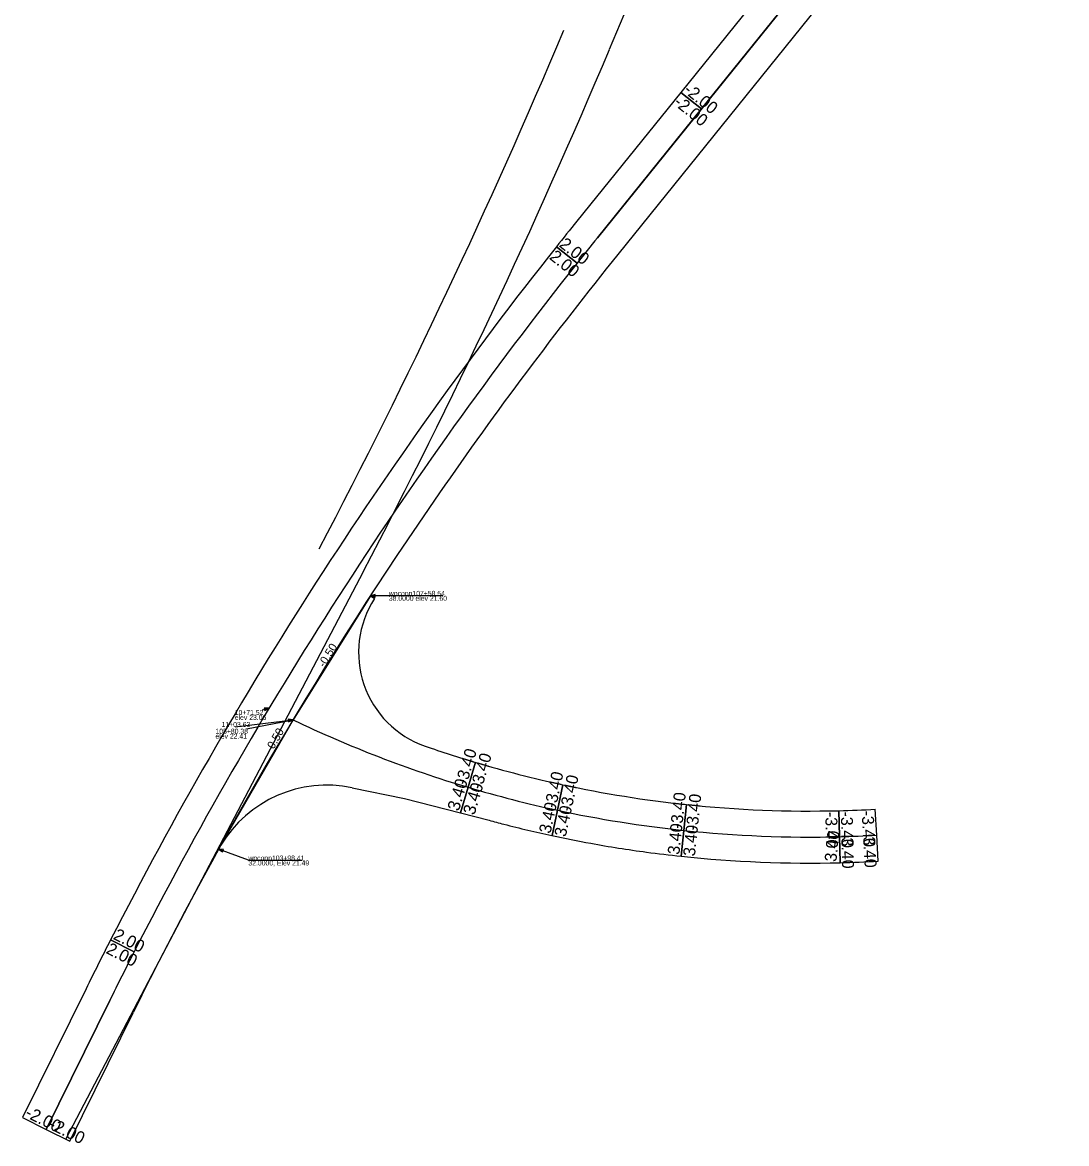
# Model space of a CAD drawing. Extents: x 2342222 to 2351711, y 366548 to 372860.
# Drawn here: x 2345362 to 2346628, y 366756 to 368114 of the extents above; entities that cross this region are included whole.
import ezdxf

# ---------------------------------------------------------------- set-up
doc = ezdxf.new("R2010")
doc.units = 0
for name, color, linetype in [('Default', 7, 'Continuous'), ('RD_HC_Cl', 7, 'Continuous'), ('RD_PD_RW_TX', 7, 'Continuous'), ('RD_PD_SuperShp_WP_CONN', 7, 'Continuous'), ('RD_Sketch4', 7, 'Continuous')]:
    doc.layers.add(name, color=color, linetype=linetype)

msp = doc.modelspace()

# ---------------------------------------------------------------- linework, layer by layer
at = {"layer": 'Default'}
for p, q in [((2345784.2, 367419.5), (2345789.2, 367416.2)), ((2346353.4, 367096.3), (2346351.8, 367159.3))]:
    msp.add_line(p, q, dxfattribs=at)
at = {"layer": 'RD_HC_Cl'}
for p, q in [((2346414.9, 368892.2), (2346073.6, 368081.3)), ((2346414.9, 368892.2), (2346073.6, 368081.3)), ((2345775.2, 367448.5), (2345415, 366761.9)), ((2345775.2, 367448.5), (2345415, 366761.9))]:
    msp.add_line(p, q, dxfattribs=at)
for radius in [8200, 8200, 8260, 8260]:
    msp.add_arc((2338460.5, 371285.5), radius, 332.32074, 337.175, dxfattribs=at)
at = {"layer": 'RD_PD_RW_TX'}
for p, q in [((2345872, 367419.5), (2345806.5, 367419.5)), ((2345701.2, 367098.9), (2345636.3, 367098.9))]:
    msp.add_line(p, q, dxfattribs=at)
for points in [[(2345790, 367421), (2345784.2, 367419.5), (2345790, 367417.9)], [(2345656.4, 367280.5), (2345661.6, 367283.5), (2345655.6, 367283.5)], [(2345685, 367266.7), (2345690.4, 367269.3), (2345684.4, 367269.8)], [(2345684.8, 367267.1), (2345690.4, 367269.3), (2345684.5, 367270.2)], [(2345606.2, 367112.1), (2345600.2, 367112.6), (2345605.1, 367109.2)]]:
    msp.add_lwpolyline(points, close=True, dxfattribs=at)
for points in [[(2345872, 367419.5), (2345784.2, 367419.5)], [(2345653, 367281.2), (2345661.6, 367283.5)], [(2345620.3, 367260.7), (2345690.4, 367269.3)], [(2345634, 367258.5), (2345690.4, 367269.3)], [(2345636.3, 367099.1), (2345600.2, 367112.6)]]:
    msp.add_lwpolyline(points, dxfattribs=at)
at = {"layer": 'RD_PD_SuperShp_WP_CONN'}
for p, q in [((2346602.8, 368577.6), (2346160.3, 368029.3)), ((2346185.2, 368009.2), (2346627.7, 368557.5)), ((2346532.1, 368439), (2346059.3, 367853.2)), ((2346084.2, 367833.1), (2346557, 368418.9)), ((2346160.3, 368029.3), (2346034.4, 367873.3)), ((2346185.2, 368009.2), (2346160.3, 368029.3)), ((2346160.3, 368029.3), (2346185.2, 368009.2)), ((2346059.3, 367853.2), (2346185.2, 368009.2)), ((2346034.6, 367822.4), (2346009.5, 367842.3)), ((2346009.5, 367842.3), (2346034.6, 367822.4)), ((2345497.9, 366988.2), (2345469.4, 367002.7)), ((2345469.4, 367002.7), (2345497.9, 366988.2)), ((2345439.6, 366943.5), (2345362.5, 366787.4)), ((2345391.2, 366773.2), (2345468.3, 366929.3)), ((2345468.3, 366929.3), (2345391.2, 366773.2)), ((2345419.9, 366759.1), (2345497, 366915.1)), ((2345419.9, 366759.1), (2345497, 366915.1)), ((2345362.5, 366787.4), (2345391.2, 366773.2)), ((2345391.2, 366773.2), (2345419.9, 366759.1))]:
    msp.add_line(p, q, dxfattribs=at)
for radius, start, end in [(5028, 141.0938, 141.5467), (4996, 141.0938, 141.5467), (4996, 141.0938, 141.5467), (5028, 141.5467, 152.9409), (4964, 141.0938, 145.2627), (4996, 141.5467, 152.9409), (4996, 141.5467, 152.9409), (4964, 145.2627, 153.6971), (5028, 152.9409, 153.6971), (4996, 152.9409, 153.6971), (4996, 152.9409, 153.6971)]:
    msp.add_arc((2349947, 364715.5), radius, start, end, dxfattribs=at)
at = {"layer": 'RD_Sketch4'}
for p, q in [((2345784.2, 367419.5), (2345690.4, 367269.3)), ((2345789.2, 367416.2), (2345784.2, 367419.5)), ((2345690.4, 367269.3), (2345602.9, 367117.4)), ((2345902.5, 367187.6), (2345911.5, 367217.8)), ((2345911.5, 367217.8), (2345902.5, 367187.6)), ((2345761.9, 367187.1), (2345825.4, 367174)), ((2345893.2, 367156.5), (2345902.5, 367187.6)), ((2345902.5, 367187.6), (2345893.2, 367156.5)), ((2346010.8, 367159.9), (2346017.5, 367190.7)), ((2346017.5, 367190.7), (2346010.8, 367159.9)), ((2345825.4, 367174), (2345893.2, 367156.5)), ((2346004.2, 367129.1), (2346010.8, 367159.9)), ((2346010.8, 367159.9), (2346004.2, 367129.1)), ((2346163.9, 367135.4), (2346167.2, 367166.7)), ((2346167.2, 367166.7), (2346163.9, 367135.4)), ((2346352.6, 367127.8), (2346351.8, 367159.3)), ((2346351.8, 367159.3), (2346352.6, 367127.8)), ((2346397.7, 367129.6), (2346395.9, 367161.1)), ((2345893.2, 367156.5), (2345928, 367147.6)), ((2346160.6, 367104), (2346163.9, 367135.4)), ((2346163.9, 367135.4), (2346160.6, 367104)), ((2346353.4, 367096.3), (2346352.6, 367127.8)), ((2346352.6, 367127.8), (2346353.4, 367096.3)), ((2346399.5, 367098.2), (2346397.7, 367129.6))]:
    msp.add_line(p, q, dxfattribs=at)
for centre, radius, start, end in [((2345889.8, 367350.8), 120, 146.9941, 250.83), ((2346316.3, 368577.7), 1450.4, 244.4328, 253.4199), ((2346316.3, 368577.7), 1450.4, 244.4328, 253.4199), ((2346316.3, 368577.7), 1418.9, 250.83, 253.4199), ((2346316.3, 368577.7), 1418.9, 253.4199, 257.8395), ((2345731.6, 367040.2), 150, 78.3222, 149.0373), ((2346316.3, 368577.7), 1450.4, 253.4199, 257.8395), ((2346316.3, 368577.7), 1450.4, 253.4199, 257.8395), ((2346316.3, 368577.7), 1418.9, 257.8395, 263.9661), ((2346316.3, 368577.7), 1450.4, 257.8395, 263.9661), ((2346316.3, 368577.7), 1450.4, 257.8395, 263.9661), ((2346316.3, 368577.7), 1418.9, 263.9661, 271.4328), ((2346316.3, 368577.7), 1418.9, 271.4328, 273.2156), ((2346316.3, 368577.7), 1481.9, 254.8096, 255.5213), ((2346316.3, 368577.7), 1481.9, 255.5213, 257.8395), ((2346316.3, 368577.7), 1450.4, 263.9661, 271.4328), ((2346316.3, 368577.7), 1450.4, 263.9661, 271.4328), ((2346316.3, 368577.7), 1481.9, 257.8395, 259.6918), ((2346316.3, 368577.7), 1481.9, 259.6918, 262.3405), ((2346316.3, 368577.7), 1450.4, 271.4328, 273.2156), ((2346316.3, 368577.7), 1450.4, 271.4328, 273.2156), ((2346316.3, 368577.7), 1481.9, 262.3405, 263.9661), ((2346316.3, 368577.7), 1481.9, 263.9661, 271.4328), ((2346316.3, 368577.7), 1481.9, 271.4328, 273.2156)]:
    msp.add_arc(centre, radius, start, end, dxfattribs=at)

# ---------------------------------------------------------------- texts
at = {"layer": 'Default'}
msp.add_text('105+80.38', height=0.00975, rotation=90, dxfattribs=at).set_placement((2345661.7, 367259.6))
msp.add_text('-.004', height=0.00975, dxfattribs=at).set_placement((2345654.6, 367222.7))
at = {"layer": 'RD_PD_RW_TX'}
for s, p in [('wpconn107+58.54', (2345806.5, 367419.5)), ('38.0000 elev 21.60', (2345806.5, 367413.5)), ('10+71.52', (2345619.8, 367275.2)), ('11+03.63', (2345603.8, 367260.7)), ('elev 23.06', (2345619.8, 367269.2)), ('elev 22.41', (2345596.4, 367246.5)), ('105+80.38', (2345596.4, 367252.5)), ('wpconn103+98.41', (2345636.3, 367098.9)), ('32.0000, Elev 21.49', (2345636.3, 367092.9))]:
    msp.add_text(s, height=6, dxfattribs=at).set_placement(p)
at = {"layer": 'RD_PD_SuperShp_WP_CONN'}
for s, rotation, p in [('-2.00', 321.0938, (2346162.7, 368030.2)), ('-2.00', 321.0938, (2346150.6, 368015.3)), ('2.00', 321.5467, (2346011.9, 367843.2)), ('2.00', 321.5467, (2346000, 367828.2)), ('2.00', 332.9409, (2345471.6, 367004.2)), ('2.00', 332.9409, (2345462.8, 366987.1)), ('-2.00', 333.6971, (2345364.6, 366788.9)), ('-2.00', 333.6971, (2345393.3, 366774.7))]:
    msp.add_text(s, height=14.72, rotation=rotation, dxfattribs=at).set_placement(p)
at = {"layer": 'RD_Sketch4'}
for s, height, rotation, p in [('-0.50', 10, 58.0157, (2345728.4, 367332)), ('-0.50', 10, 60.0807, (2345664.7, 367229.2)), ('-3.40', 14.49, 73.4199, (2345900.7, 367189.5)), ('-3.40', 14.49, 73.4199, (2345918.8, 367184.1)), ('-3.40', 14.49, 77.8395, (2346008.9, 367161.6)), ('-3.40', 14.49, 77.8395, (2346027.4, 367157.6)), ('3.40', 14.95, 73.4199, (2345891.3, 367158)), ('3.40', 14.95, 73.4199, (2345910.2, 367153.2)), ('-3.40', 14.49, 83.9661, (2346161.8, 367136.8)), ('-3.40', 14.49, 83.9661, (2346180.6, 367134.9)), ('3.40', 14.49, 77.8395, (2346002.3, 367130.8)), ('3.40', 14.49, 77.8395, (2346020.8, 367126.8)), ('-3.40', 14.49, 273.2156, (2346379.3, 367158.9)), ('-3.40', 14.49, 271.4328, (2346335.2, 367157.6)), ('-3.40', 14.49, 271.4328, (2346354.1, 367158.1)), ('3.40', 14.49, 83.9661, (2346158.5, 367105.5)), ('3.40', 14.49, 83.9661, (2346177.3, 367103.5)), ('3.40', 14.49, 83.9661, (2346348.7, 367096.8)), ('3.40', 14.49, 271.4328, (2346354.8, 367126.6)), ('3.40', 14.49, 273.2156, (2346381.1, 367127.4))]:
    msp.add_text(s, height=height, rotation=rotation, dxfattribs=at).set_placement(p)

doc.saveas('drawing.dxf')
